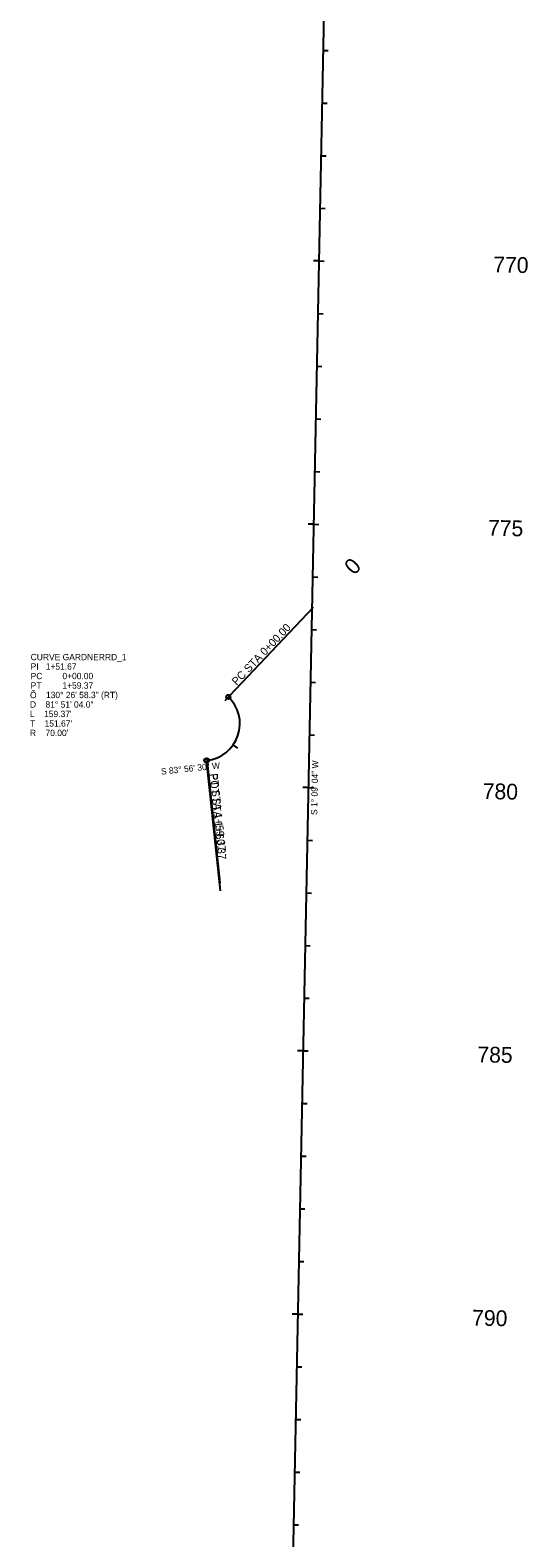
# Model space of a CAD drawing. Extents: x 2819977 to 2827606, y 116785 to 150320.
# Drawn here: x 2823203 to 2824147, y 139451 to 142313 of the extents above; entities that cross this region are included whole.
import ezdxf

# ---------------------------------------------------------------- set-up
doc = ezdxf.new("R2010")
doc.units = 0
for name, color, linetype in [('Default', 7, 'Continuous'), ('Modeling-Contours-Minor-Existing', 7, 'Continuous'), ('Modeling-Flow Arrows-Existing', 7, 'Continuous'), ('Modeling-Spot-Existing', 7, 'Continuous'), ('Modeling-Triangle Verticies-Existing', 7, 'Continuous')]:
    doc.layers.add(name, color=color, linetype=linetype)

msp = doc.modelspace()

# ---------------------------------------------------------------- linework, layer by layer
at = {"layer": 'Default'}
msp.add_arc((2823530.9, 140996.3), 70, 276.0583, 46.5078, dxfattribs=at)
at = {"layer": 'Modeling-Flow Arrows-Existing'}
for p, q in [((2823760.8, 142380.9), (2823701.1, 139408.5)), ((2823758.6, 142274.7), (2823768.6, 142274.5)), ((2823756.6, 142174.7), (2823766.6, 142174.5)), ((2823754.6, 142074.7), (2823764.6, 142074.5)), ((2823752.6, 141974.8), (2823762.6, 141974.6)), ((2823750.6, 141874.8), (2823740.6, 141875)), ((2823750.6, 141874.8), (2823760.6, 141874.6)), ((2823748.6, 141774.8), (2823758.6, 141774.6)), ((2823746.6, 141674.8), (2823756.6, 141674.6)), ((2823744.6, 141574.8), (2823754.6, 141574.6)), ((2823742.6, 141474.9), (2823752.6, 141474.7)), ((2823740.6, 141374.9), (2823730.6, 141375.1)), ((2823740.6, 141374.9), (2823750.6, 141374.7)), ((2823738.6, 141274.9), (2823748.5, 141274.7)), ((2823736.5, 141174.9), (2823746.5, 141174.7)), ((2823734.5, 141074.9), (2823744.5, 141074.7)), ((2823579.1, 141047.1), (2823572.2, 141039.8)), ((2823579.1, 141047.1), (2823586, 141054.3)), ((2823588, 140955.8), (2823596.2, 140950)), ((2823732.5, 140975), (2823742.5, 140974.8)), ((2823538.3, 140926.7), (2823537.3, 140926.6)), ((2823730.5, 140875), (2823720.5, 140875.2)), ((2823730.5, 140875), (2823740.5, 140874.8)), ((2823728.5, 140775), (2823738.5, 140774.8)), ((2823726.5, 140675), (2823736.5, 140674.8)), ((2823724.5, 140575), (2823734.5, 140574.8)), ((2823722.5, 140475.1), (2823732.5, 140474.9)), ((2823720.5, 140375.1), (2823710.5, 140375.3)), ((2823720.5, 140375.1), (2823730.5, 140374.9)), ((2823718.5, 140275.1), (2823728.5, 140274.9)), ((2823716.5, 140175.1), (2823726.5, 140174.9)), ((2823714.4, 140075.1), (2823724.4, 140074.9)), ((2823712.4, 139975.2), (2823722.4, 139975)), ((2823710.4, 139875.2), (2823700.4, 139875.4)), ((2823710.4, 139875.2), (2823720.4, 139875)), ((2823708.4, 139775.2), (2823718.4, 139775)), ((2823706.4, 139675.2), (2823716.4, 139675)), ((2823704.4, 139575.2), (2823714.4, 139575)), ((2823702.4, 139475.3), (2823712.4, 139475.1))]:
    msp.add_line(p, q, dxfattribs=at)
msp.add_arc((2823530.9, 140996.3), 70, 276.0583, 46.5078, dxfattribs=at)
at = {"layer": 'Modeling-Spot-Existing'}
for p, q in [((2823581.8, 141050), (2823740.8, 141217.5)), ((2823537.7, 140922.6), (2823563.5, 140679.2)), ((2823538.7, 140922.7), (2823563, 140694.2))]:
    msp.add_line(p, q, dxfattribs=at)
for centre in [(2823579.1, 141047.1), (2823537.3, 140926.6), (2823538.3, 140926.7)]:
    msp.add_circle(centre, 4, dxfattribs=at)

# ---------------------------------------------------------------- texts
at = {"layer": 'Modeling-Contours-Minor-Existing'}
for s, rotation, p in [('S 83%%d 56\' 30" W', 6.0583, (2823451.9, 140899.4)), ('S 1%%d 09\' 04" W', 88.849, (2823747.7, 140822.9))]:
    msp.add_text(s, height=12, rotation=rotation, dxfattribs=at).set_placement(p)
at = {"layer": 'Modeling-Flow Arrows-Existing'}
for s, rotation, p in [(' 770', 358.849, (2824070.2, 141853.4)), (' 775', 358.849, (2824060.2, 141353.5)), (' 0', 46.5078, (2823810.2, 141268.9)), (' 780', 358.849, (2824050.2, 140853.6)), (' 785', 358.849, (2824040.1, 140353.7)), (' 790', 358.849, (2824030.1, 139853.8))]:
    msp.add_text(s, height=30, rotation=rotation, dxfattribs=at).set_placement(p)
at = {"layer": 'Modeling-Spot-Existing'}
for s, rotation, p in [('PC STA 0+00.00', 46.5078, (2823594.8, 141068)), ('POT STA 1+60.37', 276.0583, (2823543, 140901)), ('PT STA 1+59.37', 276.0583, (2823544, 140901.1))]:
    msp.add_text(s, height=15, rotation=rotation, dxfattribs=at).set_placement(p)
at = {"layer": 'Modeling-Triangle Verticies-Existing'}
for s, p in [('CURVE GARDNERRD_1', (2823204, 141116.8)), ('PI   1+51.67', (2823204, 141098.8)), ('PC', (2823204, 141080.8)), ('PT', (2823204, 141062.8)), ('0+00.00', (2823264.2, 141080.8)), ('1+59.37', (2823264.2, 141062.8)), ('Õ    130%%d 26\' 58.3" (RT)', (2823202.7, 141044.8)), ('D    81%%d 51\' 04.0"', (2823202.7, 141026.8)), ("L    159.37'", (2823202.7, 141008.8)), ("T    151.67'", (2823202.7, 140990.8)), ("R    70.00'", (2823202.7, 140972.8))]:
    msp.add_text(s, height=12, dxfattribs=at).set_placement(p)

doc.saveas('drawing.dxf')
